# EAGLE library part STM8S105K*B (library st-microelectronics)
Access line, 16 MHz STM8S 8-bit MCU up to 32 Kbytes Flash, integrated EEPROM,10-bit ADC, timers, UART, SPI, I²C Source: Data sheet
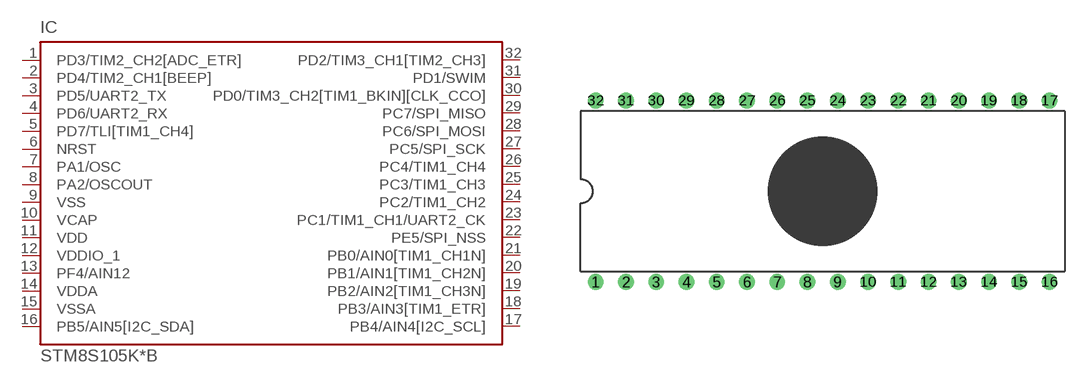
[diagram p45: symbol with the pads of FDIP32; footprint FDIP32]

Designator prefix IC

## STM8S105K4B (MPN: STM8S105K4B6; OC_FARNELL: unknown; OC_NEWARK: 55R6973), STM8S105K6B (MPN: STM8S105K6B6; OC_FARNELL: unknown; OC_NEWARK: 55R6976)  [FDIP32]
1  PD3/TIM2_CH2[ADC_ETR]
2  PD4/TIM2_CH1[BEEP]
3  PD5/UART2_TX
4  PD6/UART2_RX
5  PD7/TLI[TIM1_CH4]
6  NRST
7  PA1/OSC
8  PA2/OSCOUT
9  VSS  pwr
10  VCAP  pwr
11  VDD  pwr
12  VDDIO_1  pwr
13  PF4/AIN12
14  VDDA  pwr
15  VSSA  pwr
16  PB5/AIN5[I2C_SDA]
17  PB4/AIN4[I2C_SCL]
18  PB3/AIN3[TIM1_ETR]
19  PB2/AIN2[TIM1_CH3N]
20  PB1/AIN1[TIM1_CH2N]
21  PB0/AIN0[TIM1_CH1N]
22  PE5/SPI_NSS
23  PC1/TIM1_CH1/UART2_CK
24  PC2/TIM1_CH2
25  PC3/TIM1_CH3
26  PC4/TIM1_CH4
27  PC5/SPI_SCK
28  PC6/SPI_MOSI
29  PC7/SPI_MISO
30  PD0/TIM3_CH2[TIM1_BKIN][CLK_CCO]
31  PD1/SWIM
32  PD2/TIM3_CH1[TIM2_CH3]

## Footprint FDIP32 (pad centres in mm)
FDIP32W (F) Source: www.st.com
drill 0.813 round: 1 -19.05,-7.62; 2 -16.51,-7.62; 3 -13.97,-7.62; 4 -11.43,-7.62; 5 -8.89,-7.62; 6 -6.35,-7.62; 7 -3.81,-7.62; 8 -1.27,-7.62; 9 1.27,-7.62; 10 3.81,-7.62; 11 6.35,-7.62; 12 8.89,-7.62; 13 11.43,-7.62; 14 13.97,-7.62; 15 16.51,-7.62; 16 19.05,-7.62; 17 19.05,7.62; 18 16.51,7.62; 19 13.97,7.62; 20 11.43,7.62; 21 8.89,7.62; 22 6.35,7.62; 23 3.81,7.62; 24 1.27,7.62; 25 -1.27,7.62; 26 -3.81,7.62; 27 -6.35,7.62; 28 -8.89,7.62; 29 -11.43,7.62; 30 -13.97,7.62; 31 -16.51,7.62; 32 -19.05,7.62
